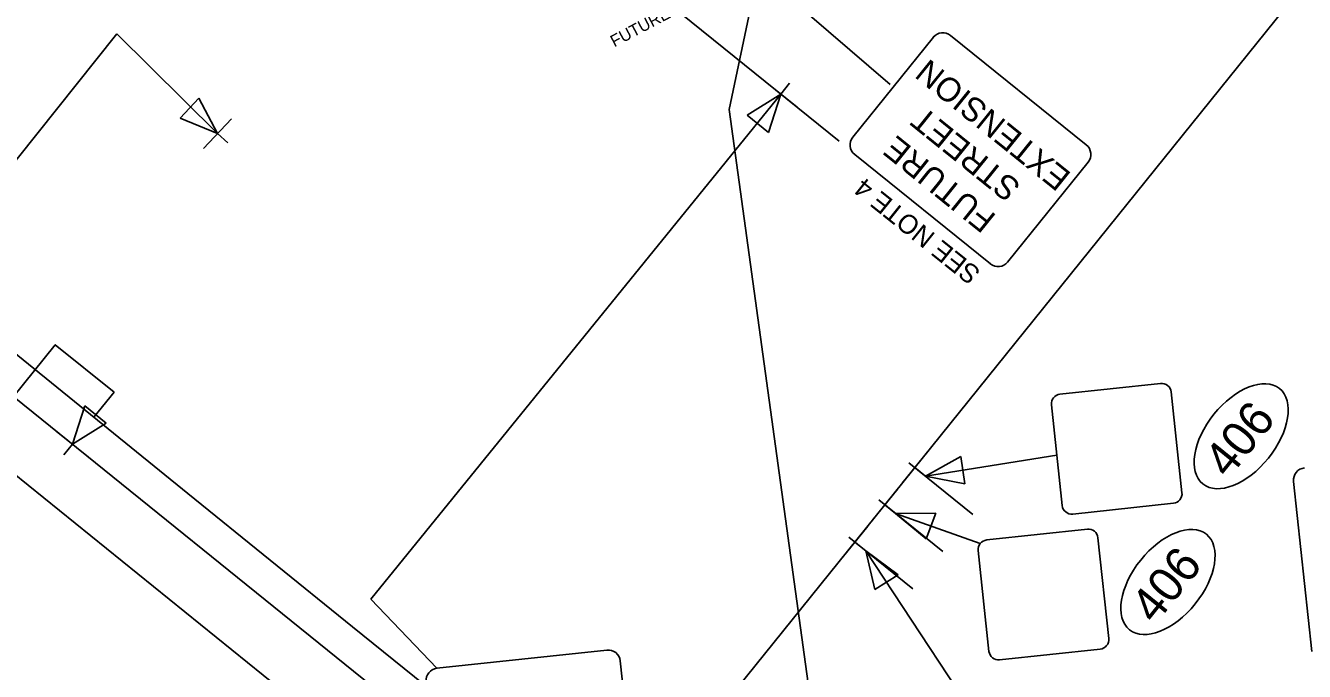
# Model space of a CAD drawing. Extents: x 1487362 to 2061618, y 497428 to 671257.
# Drawn here: x 1488633.1 to 1488847.1, y 499003.2 to 499111.2 of the extents above; entities that cross this region are included whole.
import ezdxf

# ---------------------------------------------------------------- set-up
doc = ezdxf.new("R2010")
doc.units = 0
for name, color, linetype in [('Exist Sign E', 7, 'Continuous'), ('Exist Sign E Ahead Panel CELL', 7, 'Continuous'), ('Exist Support 1', 7, 'Continuous'), ('Prop Sign E Object Marker CELL', 7, 'Continuous'), ('Prop Sign E Ped Crossing CELL', 7, 'Continuous'), ('Prop Support One', 7, 'Continuous'), ('Scratch_Level_1', 7, 'Continuous'), ('Text', 7, 'Continuous')]:
    doc.layers.add(name, color=color, linetype=linetype)

msp = doc.modelspace()

# ---------------------------------------------------------------- linework, layer by layer
at = {"layer": 'Exist Sign E'}
msp.add_line((1488845.28, 499035.01), (1488848.33, 499006.56), dxfattribs=at)
msp.add_arc((1488847.31, 499035.23), 2.04, 96.1171, 186.1171, dxfattribs=at)
at = {"layer": 'Exist Sign E Ahead Panel CELL'}
for points in [[(1488771.52, 499092.57), (1488784.99, 499109.27)], [(1488787.88, 499109.58), (1488810.58, 499091.27)], [(1488794.53, 499071.37), (1488771.83, 499089.68)], [(1488810.89, 499088.38), (1488797.42, 499071.68)]]:
    msp.add_lwpolyline(points, dxfattribs=at)
for centre, start, end in [((1488786.59, 499107.98), 51.1156, 141.1156), ((1488773.12, 499091.28), 141.1156, 231.1156), ((1488809.29, 499089.67), 321.1156, 51.1156), ((1488795.82, 499072.97), 231.1156, 321.1156)]:
    msp.add_arc(centre, 2.06, start, end, dxfattribs=at)
at = {"layer": 'Exist Support 1'}
for p, q in [((1488764.6, 499163.14), (1488750.83, 499097.17)), ((1488777.77, 499101.4), (1488747.54, 499127.39)), ((1488750.83, 499097.17), (1488765.41, 498991.5))]:
    msp.add_line(p, q, dxfattribs=at)
at = {"layer": 'Prop Sign E Object Marker CELL'}
for points in [[(1488806.18, 499049.58), (1488823.02, 499051.39)], [(1488824.8, 499049.96), (1488826.6, 499033.11)], [(1488806.55, 499030.96), (1488804.75, 499047.81)], [(1488825.17, 499031.34), (1488808.33, 499029.53)], [(1488793.92, 499025.2), (1488810.76, 499027)], [(1488812.54, 499025.57), (1488814.34, 499008.73)], [(1488794.29, 499006.58), (1488792.49, 499023.43)], [(1488812.91, 499006.96), (1488796.07, 499005.15)]]:
    msp.add_lwpolyline(points, dxfattribs=at)
for centre, start, end in [((1488823.19, 499049.78), 6.1156, 96.1156), ((1488806.35, 499047.98), 96.1156, 186.1156), ((1488825, 499032.94), 276.1156, 6.1156), ((1488808.15, 499031.14), 186.1156, 276.1156), ((1488810.94, 499025.4), 6.1156, 96.1156), ((1488794.09, 499023.6), 96.1156, 186.1156), ((1488812.74, 499008.56), 276.1156, 6.1156), ((1488795.9, 499006.75), 186.1156, 276.1156)]:
    msp.add_arc(centre, 1.61, start, end, dxfattribs=at)
for centre in [(1488836.5, 499042.56), (1488824.25, 499018.18)]:
    msp.add_ellipse(centre, major_axis=(-6.43, -7.98), ratio=0.571429, dxfattribs=at)
at = {"layer": 'Prop Sign E Ped Crossing CELL'}
for p, q in [((1488730.37, 499006.8), (1488701.92, 499003.75)), ((1488735.66, 498976.54), (1488732.61, 499004.99))]:
    msp.add_line(p, q, dxfattribs=at)
for centre, start, end in [((1488730.58, 499004.77), 6.1156, 96.1156), ((1488702.13, 499001.72), 96.1156, 186.1156)]:
    msp.add_arc(centre, 2.04, start, end, dxfattribs=at)
at = {"layer": 'Prop Support One'}
for p, q in [((1488648.35, 499109.85), (1488665.22, 499093.18)), ((1488762.13, 499097.63), (1488756.83, 499101.9)), ((1488690.86, 499015.3), (1488759.46, 499099.78)), ((1488753.82, 499096.24), (1488759.46, 499099.78)), ((1488759.46, 499099.78), (1488757.38, 499093.37)), ((1488759.46, 499099.78), (1488760.91, 499101.58)), ((1488658.97, 499095.72), (1488662.09, 499099.06)), ((1488662.09, 499099.06), (1488665.22, 499093.18)), ((1488665.22, 499093.18), (1488658.97, 499095.72)), ((1488662.88, 499090.67), (1488667.52, 499095.65)), ((1488757.38, 499093.37), (1488753.82, 499096.24)), ((1488665.22, 499093.18), (1488666.91, 499091.6)), ((1488644.5, 499045.73), (1488647.88, 499049.92)), ((1488640.91, 499041.22), (1488642.99, 499047.63)), ((1488642.99, 499047.63), (1488646.55, 499044.76)), ((1488646.55, 499044.76), (1488640.91, 499041.22)), ((1488638.24, 499043.37), (1488643.54, 499039.1)), ((1488640.91, 499041.22), (1488639.46, 499039.42)), ((1488784.05, 499040), (1488779.78, 499034.7)), ((1488783.7, 499035.88), (1488805.65, 499039.39)), ((1488783.7, 499035.88), (1488789.6, 499039.14)), ((1488789.6, 499039.14), (1488790.24, 499034.61)), ((1488781.9, 499037.33), (1488783.7, 499035.88)), ((1488790.24, 499034.61), (1488783.7, 499035.88)), ((1488779.03, 499033.77), (1488774.76, 499028.48)), ((1488776.88, 499031.1), (1488778.68, 499029.65)), ((1488778.68, 499029.65), (1488785.42, 499029.68)), ((1488778.68, 499029.65), (1488792.84, 499024.61)), ((1488783.8, 499025.4), (1488778.68, 499029.65)), ((1488785.42, 499029.68), (1488783.8, 499025.4)), ((1488774.03, 499027.53), (1488769.76, 499022.23)), ((1488771.88, 499024.86), (1488773.68, 499023.4)), ((1488775.22, 499016.93), (1488773.68, 499023.4)), ((1488773.68, 499023.4), (1488779.08, 499019.37)), ((1488773.68, 499023.4), (1488789, 499000.2)), ((1488779.08, 499019.37), (1488775.22, 499016.93)), ((1488701.92, 499003.75), (1488690.86, 499015.3))]:
    msp.add_line(p, q, dxfattribs=at)
for points in [[(1488648.35, 499109.85), (1488625.03, 499080.68)], [(1488647.88, 499049.92), (1488638.06, 499057.84), (1488572.35, 498976.36)]]:
    msp.add_lwpolyline(points, dxfattribs=at)
at = {"layer": 'Scratch_Level_1'}
for p, q in [((1488651.33, 498875.42), (1488902.43, 499186.79)), ((1488506.39, 499149.7), (1488817.76, 498898.6)), ((1488500.12, 499141.92), (1488811.48, 498890.82)), ((1488769.24, 499091.89), (1488733.52, 499120.7)), ((1488780.91, 499038.13), (1488791.62, 499029.49)), ((1488775.88, 499031.91), (1488786.59, 499023.27)), ((1488770.86, 499025.68), (1488781.57, 499017.04))]:
    msp.add_line(p, q, dxfattribs=at)
msp.add_lwpolyline([(1488989.28, 498767.5), (1488970.27, 498783.08), (1488948.72, 498800.42), (1488918.49, 498824.73), (1488883.95, 498852.55), (1488860.27, 498871.64), (1488837.77, 498889.8), (1488812.45, 498910.21), (1488784.5, 498932.73), (1488755.13, 498956.44), (1488706.79, 498995.37), (1488687.77, 499010.7), (1488660.24, 499032.99), (1488628.77, 499058.46)], dxfattribs=at)

# ---------------------------------------------------------------- texts
at = {"layer": 'Exist Sign E Ahead Panel CELL'}
for s, p in [('EXTENSION', (1488808.25, 499086.42)), ('STREET', (1488799.86, 499084.62)), ('FUTURE', (1488795.7, 499079.41))]:
    msp.add_text(s, height=4, rotation=141.1156, dxfattribs=at).set_placement(p)
at = {"layer": 'Prop Sign E Object Marker CELL'}
for p in [(1488834.36, 499035.29), (1488822.1, 499010.91)]:
    msp.add_text('406', height=5.787, rotation=51.1156, dxfattribs=at).set_placement(p)
at = {"layer": 'Scratch_Level_1'}
msp.add_text('FUTURE STREET EXTENSION', height=2, rotation=27.8351, dxfattribs=at).set_placement((1488731.61, 499107.57))
at = {"layer": 'Text'}
msp.add_text('SEE NOTE 4', height=3.2, rotation=141.2915, dxfattribs=at).set_placement((1488793.1, 499070.19))

doc.saveas('drawing.dxf')
